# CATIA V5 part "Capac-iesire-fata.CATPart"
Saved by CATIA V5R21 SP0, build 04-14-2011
Part number: Part1.2
Bounding box of the stored display mesh (mm): x -54.814 to 54.83, y 0 to 21.5, z -55 to 54.2
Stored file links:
  C:\Users\MIRCEA\Desktop\MOM\Mogan\model\Capac-iesire-fata.CATPart
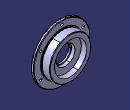
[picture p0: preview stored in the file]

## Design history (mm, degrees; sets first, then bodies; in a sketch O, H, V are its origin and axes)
Body1 (main body)
  DatumCurve1
  DatumCurve2
  Sketch1 on yz-plane, origin (0, 0, 0), H (0, 1, 0), V (0, 0, 1)
    line L1 (0, 0) -> (5, 0)
    line L2 (0, 0) -> (0, 55)
    line L3 (0, 55) -> (5, 55)
    line L4 (5, 55) -> (5, 40)
    line L5 (5, 40) -> (21.5, 40)
    line L6 (21.5, 40) -> (21.5, 31)
    line L7 (21.5, 31) -> (11.5, 31)
    line L8 (11.5, 31) -> (11.5, 18.5)
    line L9 (11.5, 18.5) -> (5, 18.5)
    point P9 (5, 18.5)
    line L10 (5, 18.5) -> (5, 0)
    length L1 = 5
    length L2 = 55
    length L4 = 15
    length L5 = 16.5
    length L6 = 9
    length L7 = 10
    length L8 = 12.5
    horizontal: L1 H, L3 H, L5 H, L7 H, L9 H
    vertical: L2 V, L4 V, L6 V, L8 V, L10 V
    coincidence: P9 L4
  Shaft1: profile Sketch1, axis Sketch1.L1, angle 360
  Sketch2 on face of Shaft1 from Sketch1.L2, origin (0, 0, 0), H (1, 0, 0), V (0, 0, 1)
    point P1 (0, 47.5)
  Sketch3 on face of Shaft1 from Sketch1.L2, origin (0, 0, 47.5), H (1, 0, 0), V (0, 0, 1)
    point P1 (0, 0)
    reference projected point E1 (0, 0) from Sketch2.P1
    coincidence: E1 P1
  Hole1: placed by Sketch3, at (0, 0, 47.5) direction (0, 1, 0), diameter 5, through (limit type 6)
  CircPattern1: of Hole1, instances 6, angular step 60 {= 360.0*1 deg/CircPattern1.AngularNumber}, axis from face of Shaft1 from Sketch1.L2
  Sketch4 on zx-plane, origin (0, 0, 0), H (-1, 0, 0), V (0, 0, 1)
    line L1 (0, 54.2) -> (14.9451, 54.2)
    line L2 (0, 54.2) -> (-11.9737, 54.2)
    line L3 (-11.9737, 54.2) -> (-11.9737, 55.4989)
    line L4 (14.9451, 54.2) -> (14.9451, 55.4989)
    line L5 (14.9451, 55.4989) -> (-11.9737, 55.4989)
    horizontal: L1 H, L2 H, L5 H
    vertical: L3 V, L4 V
  Pocket1: profile Sketch4, direction (0, 1, 0), length 20
  Sketch5 on zx-plane, origin (0, 0, 0), H (-1, 0, 0), V (0, 0, 1)
    circle A1 centre (0, 0) radius 17.5
    radius A1 = 17.5
  Pocket2: profile Sketch5, direction (0, 1, 0), through (limit type 6)
  Sketch6 on yz-plane, origin (0, 0, 0), H (0, 1, 0), V (0, 0, 1)
    point P1 (5, 41.7931)
    line L1 (5, 41.7931) -> (4.8279, 40.1066)
    arc A1 centre (5.2156, 40.067) radius 0.3896 from (4.8279, 40.1066) to (5.1458, 39.6837) ccw
    line L2 (5.1458, 39.6837) -> (5.8631, 39.6837)
    arc A2 centre (5.8631, 40.6576) radius 0.9739 from (5.8631, 39.6837) to (6.5472, 39.9644) ccw
    distance P1 V = 5
    tangency: A1 L1, A2 L1, A2 L2
    horizontal: L2 H
  Groove1: profile Sketch6, axis axis of face of Pocket2 from Sketch5.A1, angle 360
  Chamfer1: length 1, angle 45, on edge [face of Shaft1 from Sketch1.L2 | face of Shaft1 from Sketch1.L3]; edge [face of Shaft1 from Sketch1.L3 | face of Shaft1 from Sketch1.L4]; edge [face of Shaft1 from Sketch1.L5 | face of Shaft1 from Sketch1.L6]; edge [face of Pocket2 from Sketch5.A1 | face of Shaft1 from Sketch1.L2]; edge [face of Shaft1 from Sketch1.L10 | face of Pocket2 from Sketch5.A1]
